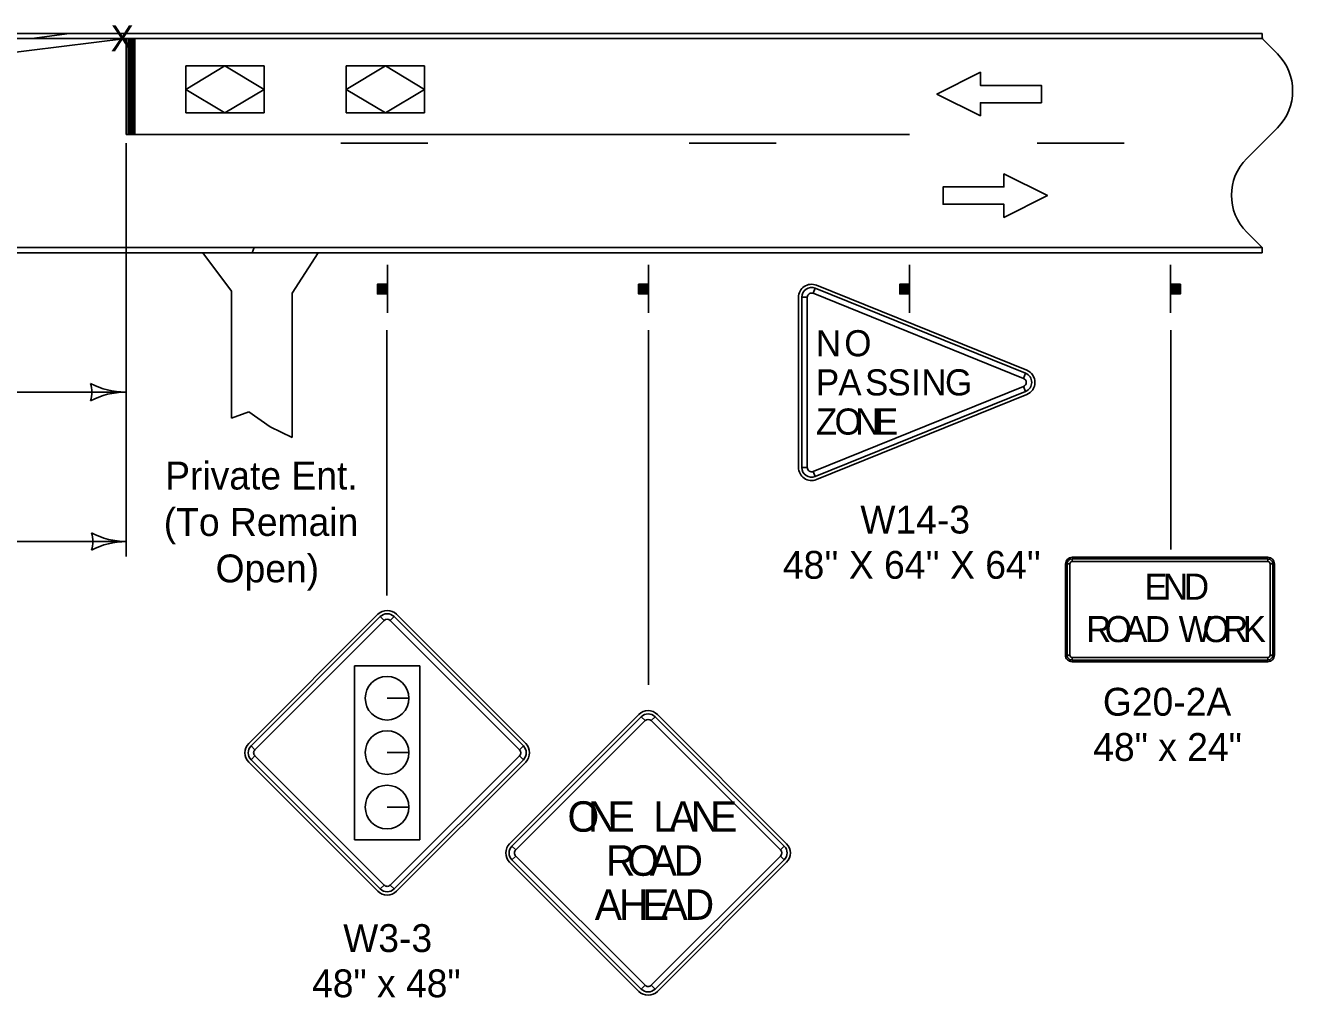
# Model space of a CAD drawing. Extents: x 10124 to 16850, y 7924 to 12166.
# Drawn here: x 16036 to 16764, y 8874 to 9432 of the extents above; entities that cross this region are included whole.
import ezdxf

# ---------------------------------------------------------------- set-up
doc = ezdxf.new("R2010")
doc.units = 0
for name, color, linetype in [('dsnCellElements', 7, 'Continuous'), ('dsnStdLabel', 7, 'Continuous'), ('dsnStdLineWork', 7, 'Continuous'), ('Level 2', 7, 'Continuous'), ('Level 4', 7, 'Continuous')]:
    doc.layers.add(name, color=color, linetype=linetype)

msp = doc.modelspace()

# ---------------------------------------------------------------- linework, layer by layer
at = {"layer": 'dsnCellElements'}
for centre, radius, start, end in [((16058.64, 9135.85), 16.42, 342.26665, 17.73335), ((16094.27, 9178.35), 42.5, 241.92751, 270), ((16094.27, 9093.35), 42.5, 90, 118.07249)]:
    msp.add_arc(centre, radius, start, end, dxfattribs=at)
at = {"layer": 'dsnStdLabel'}
for p, q in [((16611.57, 9234.25), (16490.75, 9283.13)), ((16480.44, 9276.17), (16480.44, 9178.42)), ((16482.31, 9276.17), (16485.44, 9276.17)), ((16488.87, 9278.49), (16490.05, 9281.39)), ((16610.87, 9232.51), (16609.7, 9229.62)), ((16609.7, 9224.98), (16610.87, 9222.08)), ((16490.75, 9171.47), (16611.57, 9220.35)), ((16485.44, 9178.42), (16482.31, 9178.42)), ((16490.05, 9173.21), (16488.87, 9176.1)), ((16633.81, 9123.06), (16633.81, 9070.56)), ((16634.75, 9123.06), (16636.31, 9123.06)), ((16750.06, 9126.81), (16637.56, 9126.81)), ((16637.56, 9124.31), (16637.56, 9125.87)), ((16750.06, 9125.87), (16750.06, 9124.31)), ((16751.31, 9123.06), (16752.87, 9123.06)), ((16753.81, 9070.56), (16753.81, 9123.06)), ((16238.85, 9094.04), (16164.6, 9019.79)), ((16323.7, 9019.79), (16249.46, 9094.04)), ((16240.18, 9092.71), (16242.39, 9090.51)), ((16245.92, 9090.51), (16248.13, 9092.71)), ((16636.31, 9070.56), (16634.75, 9070.56)), ((16637.56, 9067.74), (16637.56, 9069.31)), ((16637.56, 9066.81), (16750.06, 9066.81)), ((16750.06, 9069.31), (16750.06, 9067.74)), ((16752.87, 9070.56), (16751.31, 9070.56)), ((16256.56, 9045.82), (16244.06, 9045.82)), ((16244.06, 9045.82), (16256.56, 9045.82)), ((16388.74, 9036.5), (16314.49, 8962.25)), ((16390.06, 9035.17), (16392.27, 9032.96)), ((16395.81, 9032.96), (16398.02, 9035.17)), ((16473.59, 8962.25), (16399.34, 9036.5)), ((16168.14, 9016.26), (16165.93, 9018.47)), ((16256.56, 9014.57), (16244.06, 9014.57)), ((16244.06, 9014.57), (16256.56, 9014.57)), ((16322.38, 9018.47), (16320.17, 9016.26)), ((16164.6, 9009.19), (16238.85, 8934.94)), ((16165.93, 9010.51), (16168.14, 9012.72)), ((16249.46, 8934.94), (16323.7, 9009.19)), ((16320.17, 9012.72), (16322.38, 9010.51)), ((16256.56, 8983.32), (16244.06, 8983.32)), ((16244.06, 8983.32), (16256.56, 8983.32)), ((16318.02, 8958.71), (16315.82, 8960.92)), ((16315.82, 8952.97), (16318.02, 8955.18)), ((16472.26, 8960.92), (16470.05, 8958.71)), ((16470.05, 8955.18), (16472.26, 8952.97)), ((16314.49, 8951.64), (16388.74, 8877.4)), ((16399.34, 8877.4), (16473.59, 8951.64)), ((16242.39, 8938.48), (16240.18, 8936.27)), ((16248.13, 8936.27), (16245.92, 8938.48)), ((16392.27, 8880.93), (16390.06, 8878.72)), ((16398.02, 8878.72), (16395.81, 8880.93))]:
    msp.add_line(p, q, dxfattribs=at)
for points in [[(16482.31, 9276.17), (16482.31, 9178.42), (16485.44, 9178.42), (16485.44, 9276.17), (16482.31, 9276.17)], [(16610.87, 9232.51), (16490.05, 9281.39), (16488.87, 9278.49), (16609.7, 9229.62), (16610.87, 9232.51)], [(16490.05, 9173.21), (16610.87, 9222.08), (16609.7, 9224.98), (16488.87, 9176.1), (16490.05, 9173.21)], [(16634.75, 9123.06), (16634.75, 9070.56), (16636.31, 9070.56), (16636.31, 9123.06), (16634.75, 9123.06)], [(16750.06, 9125.87), (16637.56, 9125.87), (16637.56, 9124.31), (16750.06, 9124.31), (16750.06, 9125.87)], [(16752.87, 9070.56), (16752.87, 9123.06), (16751.31, 9123.06), (16751.31, 9070.56), (16752.87, 9070.56)], [(16240.18, 9092.71), (16165.93, 9018.47), (16168.14, 9016.26), (16242.39, 9090.51), (16240.18, 9092.71)], [(16322.38, 9018.47), (16248.13, 9092.71), (16245.92, 9090.51), (16320.17, 9016.26), (16322.38, 9018.47)], [(16262.88, 9064.43), (16225.42, 9064.43), (16225.42, 8964.55), (16262.88, 8964.55), (16262.88, 9064.43)], [(16637.56, 9067.74), (16750.06, 9067.74), (16750.06, 9069.31), (16637.56, 9069.31), (16637.56, 9067.74)], [(16390.06, 9035.17), (16315.82, 8960.92), (16318.02, 8958.71), (16392.27, 9032.96), (16390.06, 9035.17)], [(16472.26, 8960.92), (16398.02, 9035.17), (16395.81, 9032.96), (16470.05, 8958.71), (16472.26, 8960.92)], [(16165.93, 9010.51), (16240.18, 8936.27), (16242.39, 8938.48), (16168.14, 9012.72), (16165.93, 9010.51)], [(16248.13, 8936.27), (16322.38, 9010.51), (16320.17, 9012.72), (16245.92, 8938.48), (16248.13, 8936.27)], [(16315.82, 8952.97), (16390.06, 8878.72), (16392.27, 8880.93), (16318.02, 8955.18), (16315.82, 8952.97)], [(16398.02, 8878.72), (16472.26, 8952.97), (16470.05, 8955.18), (16395.81, 8880.93), (16398.02, 8878.72)]]:
    msp.add_lwpolyline(points, close=True, dxfattribs=at)
for centre in [(16244.06, 9045.82), (16244.06, 9014.57), (16244.06, 8983.32)]:
    msp.add_circle(centre, 12.5, dxfattribs=at)
for centre, radius, start, end in [((16487.94, 9276.17), 7.5, 67.97571, 179.99985), ((16487.94, 9276.17), 5.62, 67.97571, 179.99985), ((16487.94, 9276.17), 2.5, 67.97571, 179.99985), ((16608.76, 9227.3), 5.62, 292.02456, 67.97541), ((16608.76, 9227.3), 7.5, 292.02456, 67.97598), ((16608.76, 9227.3), 2.5, 292.02456, 67.97541), ((16487.94, 9178.42), 7.5, 179.99985, 292.02456), ((16487.94, 9178.42), 5.62, 179.99985, 292.02456), ((16487.94, 9178.42), 2.5, 179.99985, 292.02456), ((16637.56, 9123.06), 3.75, 90.00021, 179.99985), ((16637.56, 9123.06), 2.81, 90.00021, 179.99985), ((16637.56, 9123.06), 1.25, 90.00021, 179.99985), ((16750.06, 9123.06), 3.75, 0, 90.00021), ((16750.06, 9123.06), 2.81, 0, 90.00021), ((16750.06, 9123.06), 1.25, 0, 90.00021), ((16244.15, 9088.74), 7.5, 44.99999, 134.99974), ((16244.15, 9088.74), 5.62, 44.99999, 134.99974), ((16244.15, 9088.74), 2.5, 44.99999, 134.99974), ((16637.56, 9070.56), 3.75, 179.99985, 270.00006), ((16637.56, 9070.56), 2.81, 179.99985, 270.00006), ((16637.56, 9070.56), 1.25, 179.99985, 270.00006), ((16750.06, 9070.56), 3.75, 270.00006, 0.00027), ((16750.06, 9070.56), 2.81, 270.00006, 0.00027), ((16750.06, 9070.56), 1.25, 270.00006, 0.00027), ((16394.04, 9031.19), 7.5, 44.99999, 134.99974), ((16394.04, 9031.19), 5.62, 44.99999, 134.99974), ((16394.04, 9031.19), 2.5, 44.99999, 134.99974), ((16169.91, 9014.49), 7.5, 134.99974, 224.99995), ((16169.91, 9014.49), 5.62, 134.99974, 224.99995), ((16169.91, 9014.49), 2.5, 134.99974, 224.99995), ((16318.4, 9014.49), 2.5, 315.00016, 44.9998), ((16318.4, 9014.49), 5.62, 315.00016, 44.9998), ((16318.4, 9014.49), 7.5, 315.00016, 44.9998), ((16319.79, 8956.95), 7.5, 134.99974, 224.99995), ((16468.28, 8956.95), 7.5, 315.00016, 44.9998), ((16319.79, 8956.95), 5.62, 134.99974, 224.99995), ((16319.79, 8956.95), 2.5, 134.99974, 224.99995), ((16468.28, 8956.95), 2.5, 315.00016, 44.9998), ((16468.28, 8956.95), 5.62, 315.00016, 44.9998), ((16244.15, 8940.24), 7.5, 224.99995, 315.00016), ((16244.15, 8940.24), 5.62, 224.99995, 315.00016), ((16244.15, 8940.24), 2.5, 224.99995, 315.00016), ((16394.04, 8882.7), 7.5, 224.99995, 315.00016), ((16394.04, 8882.7), 5.62, 224.99995, 315.00016), ((16394.04, 8882.7), 2.5, 224.99995, 315.00016)]:
    msp.add_arc(centre, radius, start, end, dxfattribs=at)
at = {"layer": 'dsnStdLineWork'}
for p, q in [((15747.08, 9424.79), (16040.03, 9424.79)), ((16061.71, 9427.79), (15748.05, 9427.79)), ((16061.71, 9427.79), (16040.03, 9424.79)), ((16040.03, 9424.79), (16061.71, 9427.79)), ((16040.03, 9424.79), (16094.27, 9424.79)), ((16746.73, 9427.79), (16061.71, 9427.79)), ((16099.27, 9424.79), (16746.73, 9424.79)), ((16746.73, 9427.79), (16746.73, 9424.79)), ((16746.73, 9424.79), (16746.73, 9427.79)), ((16094.27, 9369.79), (16544.27, 9369.79)), ((16217.57, 9364.79), (16267.57, 9364.79)), ((16417.57, 9364.79), (16417.57, 9364.79)), ((16417.57, 9364.79), (16467.57, 9364.79)), ((16617.57, 9364.79), (16617.57, 9364.79)), ((16617.57, 9364.79), (16667.57, 9364.79)), ((15244.27, 9304.79), (16746.73, 9304.79)), ((15244.27, 9304.79), (16746.73, 9304.79)), ((16167.67, 9304.79), (15893.78, 9304.79)), ((16166.66, 9301.79), (16167.67, 9304.79)), ((16167.67, 9304.79), (16166.66, 9301.79)), ((16746.73, 9304.79), (16167.67, 9304.79)), ((16746.73, 9301.79), (16746.73, 9304.79)), ((16746.73, 9301.79), (16746.73, 9304.79)), ((15244.27, 9301.79), (16746.73, 9301.79)), ((15893.78, 9301.79), (16166.66, 9301.79)), ((16138.33, 9301.73), (16154.64, 9279.77)), ((16204.57, 9301.73), (16138.33, 9301.73)), ((16166.66, 9301.79), (16746.73, 9301.79)), ((16189.63, 9278.62), (16204.57, 9301.73)), ((16154.64, 9279.77), (16154.64, 9206.65)), ((16189.63, 9195.64), (16189.63, 9278.62)), ((16154.64, 9206.65), (16164.67, 9210.42)), ((16164.67, 9210.42), (16176.94, 9201.81)), ((16176.94, 9201.81), (16189.63, 9195.64))]:
    msp.add_line(p, q, dxfattribs=at)
for points in [[(15434.27, 9427.79), (16746.73, 9427.79)], [(15434.27, 9424.79), (16746.73, 9424.79)], [(15434.97, 9424.79), (16747.43, 9424.79)], [(16094.27, 9424.79), (16095.27, 9424.79), (16096.27, 9424.79)], [(16096.27, 9424.79), (16097.27, 9424.79), (16098.27, 9424.79), (16099.27, 9424.79)]]:
    msp.add_lwpolyline(points, dxfattribs=at)
at = {"layer": 'Level 2'}
for p, q in [((16746.73, 9424.79), (15434.27, 9424.79)), ((16094.27, 9424.79), (15606.41, 9364.79)), ((16094.27, 9424.79), (16094.27, 9369.79)), ((16095.27, 9424.79), (16095.27, 9369.79)), ((16096.27, 9424.79), (16096.27, 9369.79)), ((16097.27, 9424.79), (16097.27, 9369.79)), ((16098.27, 9424.79), (16098.27, 9369.79)), ((16099.27, 9424.79), (16099.27, 9369.79)), ((16755.51, 9416), (16746.73, 9424.79)), ((16755.51, 9416), (16746.73, 9424.79)), ((16128.44, 9382.16), (16128.44, 9409.16)), ((16128.44, 9409.16), (16173.44, 9409.16)), ((16128.44, 9382.16), (16128.44, 9409.16)), ((16128.44, 9409.16), (16173.44, 9409.16)), ((16173.44, 9409.16), (16128.44, 9409.16)), ((16128.44, 9409.16), (16128.44, 9382.16)), ((16173.44, 9382.16), (16173.44, 9409.16)), ((16173.44, 9409.16), (16173.44, 9382.16)), ((16173.44, 9382.16), (16173.44, 9409.16)), ((16220.63, 9382.08), (16220.63, 9409.08)), ((16220.63, 9409.08), (16265.63, 9409.08)), ((16220.63, 9382.08), (16220.63, 9409.08)), ((16220.63, 9409.08), (16265.63, 9409.08)), ((16265.63, 9409.08), (16220.63, 9409.08)), ((16220.63, 9409.08), (16220.63, 9382.08)), ((16265.63, 9382.08), (16265.63, 9409.08)), ((16265.63, 9409.08), (16265.63, 9382.08)), ((16265.63, 9382.08), (16265.63, 9409.08)), ((16128.44, 9382.16), (16173.44, 9382.16)), ((16173.44, 9382.16), (16128.44, 9382.16)), ((16128.44, 9382.16), (16173.44, 9382.16)), ((16220.63, 9382.08), (16265.63, 9382.08)), ((16265.63, 9382.08), (16220.63, 9382.08)), ((16220.63, 9382.08), (16265.63, 9382.08)), ((16737.94, 9356), (16755.51, 9373.57)), ((16737.94, 9356), (16755.51, 9373.57)), ((16094.27, 9127.18), (16094.27, 9364.79)), ((16746.73, 9304.79), (16737.94, 9313.57)), ((16746.73, 9304.79), (16737.94, 9313.57)), ((15244.27, 9304.79), (16746.73, 9304.79)), ((16244.27, 9267.29), (16244.27, 9294.79)), ((16394.27, 9267.29), (16394.27, 9294.79)), ((16544.27, 9267.29), (16544.27, 9294.79)), ((16694.08, 9267.29), (16694.08, 9294.79)), ((16238.95, 9278.15), (16238.95, 9283.73)), ((16239.27, 9283.73), (16239.27, 9278.15)), ((16239.49, 9278.15), (16239.49, 9283.73)), ((16239.81, 9283.73), (16239.81, 9278.15)), ((16240.03, 9278.15), (16240.02, 9283.73)), ((16240.45, 9283.73), (16240.47, 9278.15)), ((16240.67, 9278.15), (16240.67, 9283.73)), ((16241.1, 9283.73), (16241.1, 9278.15)), ((16241.48, 9278.15), (16241.48, 9283.73)), ((16241.8, 9283.73), (16241.82, 9278.15)), ((16242.02, 9278.15), (16242.02, 9283.73)), ((16242.28, 9283.73), (16242.28, 9278.15)), ((16242.62, 9278.15), (16242.62, 9283.73)), ((16242.83, 9283.73), (16242.83, 9278.15)), ((16243.05, 9278.15), (16243.05, 9283.73)), ((16243.32, 9283.73), (16243.32, 9278.15)), ((16243.58, 9278.15), (16243.58, 9283.73)), ((16243.86, 9283.73), (16243.86, 9278.15)), ((16388.95, 9278.15), (16388.95, 9283.73)), ((16389.27, 9283.73), (16389.27, 9278.15)), ((16389.49, 9278.15), (16389.49, 9283.73)), ((16389.81, 9283.73), (16389.81, 9278.15)), ((16390.03, 9278.15), (16390.02, 9283.73)), ((16390.45, 9283.73), (16390.47, 9278.15)), ((16390.67, 9278.15), (16390.67, 9283.73)), ((16391.1, 9283.73), (16391.1, 9278.15)), ((16391.48, 9278.15), (16391.48, 9283.73)), ((16391.8, 9283.73), (16391.82, 9278.15)), ((16392.02, 9278.15), (16392.02, 9283.73)), ((16392.28, 9283.73), (16392.28, 9278.15)), ((16392.62, 9278.15), (16392.62, 9283.73)), ((16392.83, 9283.73), (16392.83, 9278.15)), ((16393.05, 9278.15), (16393.05, 9283.73)), ((16393.32, 9283.73), (16393.32, 9278.15)), ((16393.58, 9278.15), (16393.58, 9283.73)), ((16393.86, 9283.73), (16393.86, 9278.15)), ((16538.95, 9278.15), (16538.95, 9283.73)), ((16539.27, 9283.73), (16539.27, 9278.15)), ((16539.49, 9278.15), (16539.49, 9283.73)), ((16539.81, 9283.73), (16539.81, 9278.15)), ((16540.03, 9278.15), (16540.02, 9283.73)), ((16540.45, 9283.73), (16540.47, 9278.15)), ((16540.67, 9278.15), (16540.67, 9283.73)), ((16541.1, 9283.73), (16541.1, 9278.15)), ((16541.48, 9278.15), (16541.48, 9283.73)), ((16541.8, 9283.73), (16541.82, 9278.15)), ((16542.02, 9278.15), (16542.02, 9283.73)), ((16542.28, 9283.73), (16542.28, 9278.15)), ((16542.62, 9278.15), (16542.62, 9283.73)), ((16542.83, 9283.73), (16542.83, 9278.15)), ((16543.05, 9278.15), (16543.05, 9283.73)), ((16543.32, 9283.73), (16543.32, 9278.15)), ((16543.58, 9278.15), (16543.58, 9283.73)), ((16543.86, 9283.73), (16543.86, 9278.15)), ((16694.49, 9283.73), (16694.49, 9278.15)), ((16694.78, 9278.15), (16694.78, 9283.73)), ((16695.04, 9283.73), (16695.04, 9278.15)), ((16695.3, 9278.15), (16695.3, 9283.73)), ((16695.53, 9283.73), (16695.53, 9278.15)), ((16695.73, 9278.15), (16695.73, 9283.73)), ((16696.07, 9283.73), (16696.07, 9278.15)), ((16696.33, 9278.15), (16696.33, 9283.73)), ((16696.56, 9283.73), (16696.54, 9278.15)), ((16696.88, 9278.15), (16696.88, 9283.73)), ((16697.25, 9283.73), (16697.25, 9278.15)), ((16697.68, 9278.15), (16697.68, 9283.73)), ((16697.91, 9283.73), (16697.89, 9278.15)), ((16698.32, 9278.15), (16698.34, 9283.73)), ((16698.55, 9283.73), (16698.55, 9278.15)), ((16698.86, 9278.15), (16698.86, 9283.73)), ((16699.09, 9283.73), (16699.09, 9278.15)), ((16699.41, 9278.15), (16699.41, 9283.73)), ((16243.98, 9104.88), (16243.98, 9257.29)), ((16394.27, 9053.57), (16394.27, 9257.29)), ((16694.27, 9131.23), (16694.27, 9257.29)), ((15975.18, 9221.71), (16094.27, 9221.71)), ((15879.27, 9135.85), (16094.27, 9135.85))]:
    msp.add_line(p, q, dxfattribs=at)
for points in [[(16619.97, 9387.95), (16619.97, 9397.95), (16584.97, 9397.95), (16584.97, 9405.45), (16559.97, 9392.95), (16584.97, 9380.45), (16584.97, 9387.95)], [(16563.46, 9339.61), (16563.46, 9329.61), (16598.46, 9329.61), (16598.46, 9322.11), (16623.46, 9334.61), (16598.46, 9347.11), (16598.46, 9339.61)], [(16244.18, 9283.73), (16244.18, 9278.11), (16238.55, 9278.11), (16238.55, 9283.73)], [(16394.18, 9283.73), (16394.18, 9278.11), (16388.55, 9278.11), (16388.55, 9283.73)], [(16544.18, 9283.73), (16544.18, 9278.11), (16538.55, 9278.11), (16538.55, 9283.73)], [(16694.18, 9283.73), (16694.18, 9278.11), (16699.8, 9278.11), (16699.8, 9283.73)]]:
    msp.add_lwpolyline(points, close=True, dxfattribs=at)
for points in [[(16584.97, 9387.95), (16584.97, 9380.45), (16559.97, 9392.95), (16584.97, 9405.45), (16584.97, 9397.95), (16619.97, 9397.95), (16619.97, 9387.95), (16584.97, 9387.95)], [(16598.46, 9339.61), (16598.46, 9347.11), (16623.46, 9334.61), (16598.46, 9322.11), (16598.46, 9329.61), (16563.46, 9329.61), (16563.46, 9339.61), (16598.46, 9339.61)]]:
    msp.add_lwpolyline(points, dxfattribs=at)
for centre, radius, start, end in [((16734.3, 9394.79), 30, 315, 45), ((16734.3, 9394.79), 30, 315, 45), ((16759.15, 9334.79), 30, 135, 225), ((16759.15, 9334.79), 30, 135, 225), ((16058.15, 9221.71), 16.42, 342.26665, 17.73335), ((16093.78, 9264.21), 42.5, 241.92751, 270), ((16093.78, 9179.21), 42.5, 90, 118.07249)]:
    msp.add_arc(centre, radius, start, end, dxfattribs=at)
at = {"layer": 'Level 4'}
for points in [[(16128.44, 9395.66), (16150.94, 9409.16), (16173.44, 9395.66), (16150.94, 9382.16)], [(16220.63, 9395.58), (16243.13, 9409.08), (16265.63, 9395.58), (16243.13, 9382.08)]]:
    msp.add_lwpolyline(points, close=True, dxfattribs=at)

# ---------------------------------------------------------------- texts
at = {"layer": 'dsnStdLabel'}
for s, height, p in [('N', 15, (16490.41, 9242.3)), ('O', 15, (16506.74, 9242.3)), ('P', 15, (16490.41, 9219.8)), ('A', 15, (16503.3, 9219.8)), ('S', 15, (16518.65, 9219.8)), ('S', 15, (16531.54, 9219.8)), ('I', 15, (16545.13, 9219.8)), ('N', 15, (16550.99, 9219.8)), ('G', 15, (16564.59, 9219.8)), ('Z', 15, (16490.41, 9197.3)), ('O', 15, (16501.14, 9197.3)), ('N', 15, (16512.97, 9197.3)), ('E', 15, (16524.33, 9197.3)), ('E', 15, (16679.14, 9102.43)), ('N', 15, (16689.75, 9102.43)), ('D', 15, (16701.84, 9102.43)), ('R', 15, (16645.67, 9078.06)), ('O', 15, (16656.36, 9078.06)), ('A', 15, (16667.51, 9078.06)), ('D', 15, (16679.37, 9078.06)), ('W', 15, (16698.82, 9078.06)), ('O', 15, (16712.56, 9078.06)), ('R', 15, (16724.32, 9078.06)), ('K', 15, (16735.62, 9078.06)), ('O', 17.5, (16347.75, 8969.13)), ('N', 17.5, (16359.53, 8969.13)), ('E', 17.5, (16370.76, 8969.13)), ('L', 17.5, (16397.01, 8969.13)), ('A', 17.5, (16406.2, 8969.13)), ('N', 17.5, (16418.47, 8969.13)), ('E', 17.5, (16429.7, 8969.13)), ('R', 17.5, (16369.86, 8943.82)), ('O', 17.5, (16382.15, 8943.82)), ('A', 17.5, (16394.99, 8943.82)), ('D', 17.5, (16408.64, 8943.82)), ('A', 17.5, (16363.42, 8918.51)), ('H', 17.5, (16377.29, 8918.51)), ('E', 17.5, (16390.51, 8918.51)), ('A', 17.5, (16401.22, 8918.51)), ('D', 17.5, (16415.08, 8918.51))]:
    msp.add_text(s, height=height, dxfattribs=at).set_placement(p)
at = {"layer": 'Level 2'}
for s, height, p in [('X', 15, (16085.27, 9417.44)), ('Private Ent.', 16, (16116.61, 9165.75)), ('(To Remain', 16, (16115.79, 9139.08)), ('W14-3', 16, (16515.95, 9140.47)), ("48'' X 64'' X 64''", 16, (16471.46, 9114.47)), (' Open)', 16, (16139.64, 9112.42)), ('G20-2A', 16, (16655.28, 9035.81)), ('48" x 24"', 16, (16649.74, 9009.81)), ('W3-3', 16, (16218.86, 8900.02)), ('48" x 48"', 16, (16200.98, 8874.02))]:
    msp.add_text(s, height=height, dxfattribs=at).set_placement(p)

doc.saveas('drawing.dxf')
